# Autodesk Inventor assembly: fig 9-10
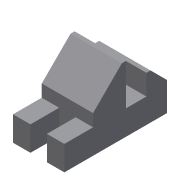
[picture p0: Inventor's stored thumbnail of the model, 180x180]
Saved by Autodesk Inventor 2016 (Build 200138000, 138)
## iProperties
Shininess: 64.0
Length Units: 11269
Angle Units: 11279
Time Units: 11290
Mass Units: 11283
Length Display Precision: 3
Angle Display Precision: 2
Created: 2002-01
Part Number: fig 9-10
Document SubType Name: Assembly
Designer: ***
Density: 0.0
Volumn: 0.0
Area: 0.0
PropertySet Name: Model Information
Control State: 0
Master: False
Checked Out: False
Author: ***
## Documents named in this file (3)
- D:\KAVITA\Autodesk Inventor_ 2016 Project_Kavita\Inventor_Part Files\Inventor_2016_Part\c09_Inv_2016\c09_inv_2016_prt\fig 9-10.iam
- D:\KAVITA\Autodesk Inventor_ 2016 Project_Kavita\Inventor_Part Files\Inventor_2016_Part\c09_Inv_2016\c09_inv_2016_prt\Part3.ipt
- D:\KAVITA\Autodesk Inventor_ 2016 Project_Kavita\Inventor_Part Files\Inventor_2016_Part\c09_Inv_2016\c09_inv_2016_prt\Part4.ipt
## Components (2 placed, 2 different names)
1. Part3:1
2. Part4:1
